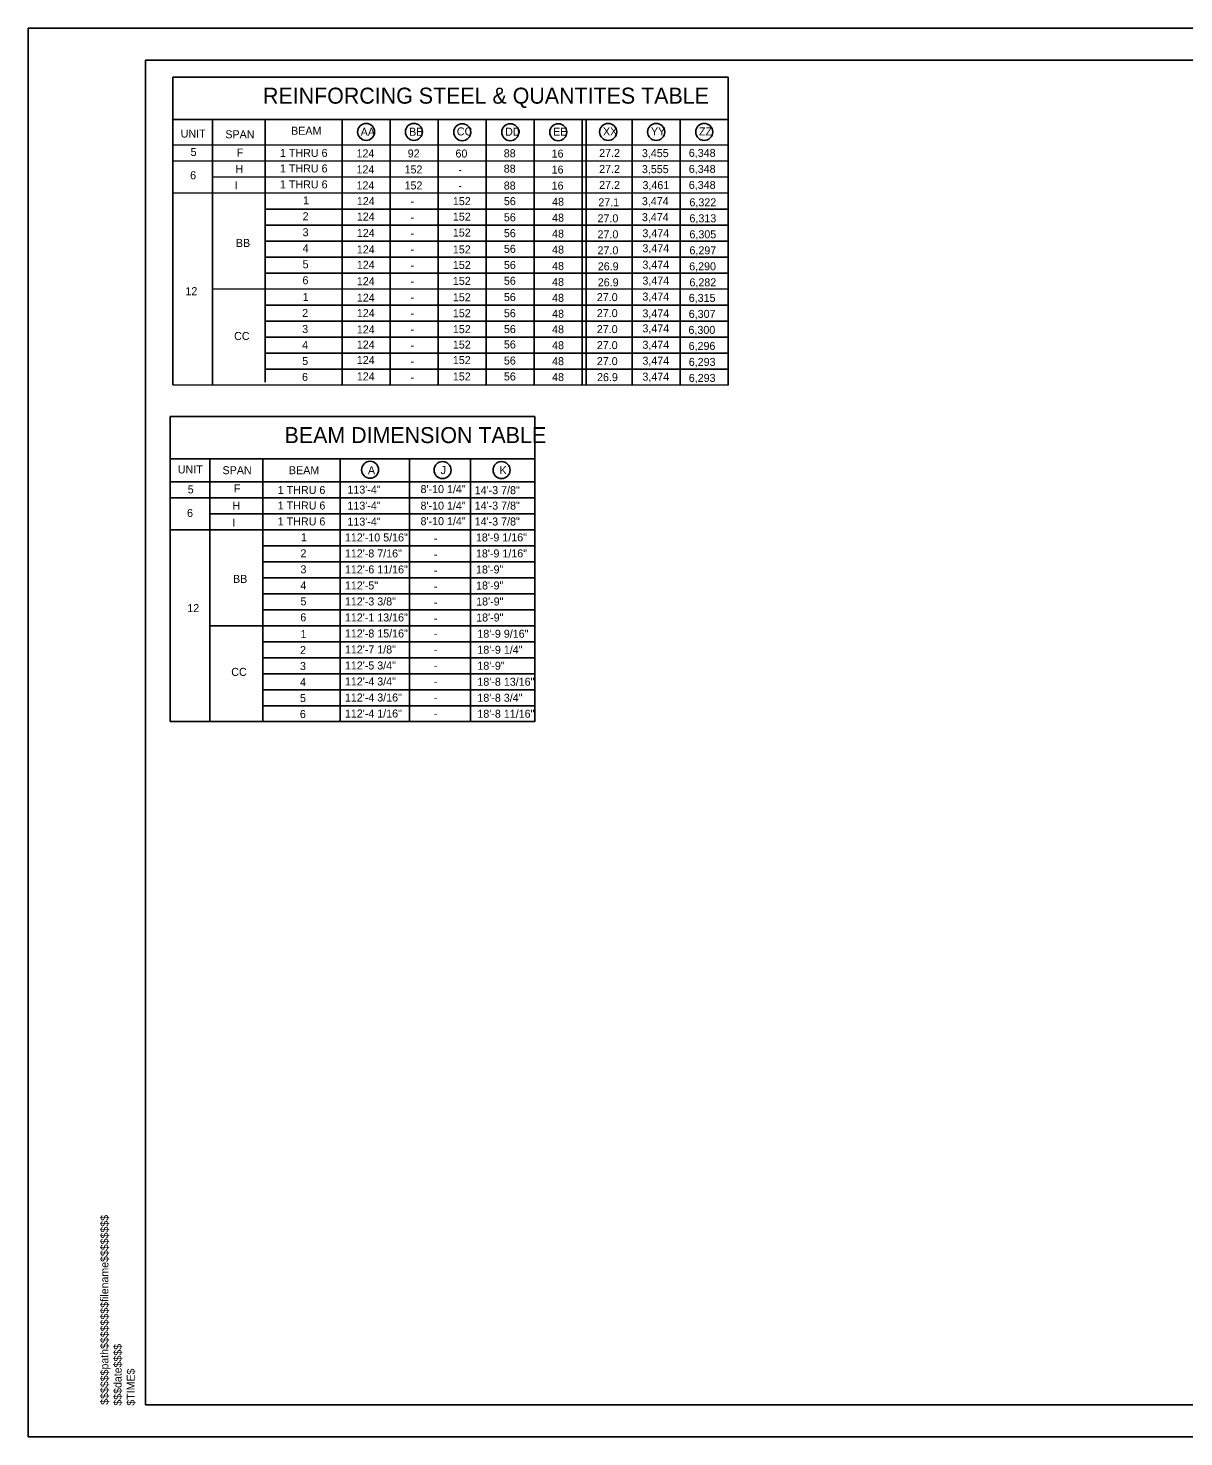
# Model space of a CAD drawing. Extents: x -55.6 to -19.5, y -100.1 to -78.1.
# Drawn here: x -55.58 to -37.53, y -100.12 to -78.12 of the extents above; entities that cross this region are included whole.
import ezdxf

# ---------------------------------------------------------------- set-up
doc = ezdxf.new("R2010")
doc.units = 0
for name, color, linetype in [('BR_AUTO DIMENSION', 7, 'Continuous'), ('BR_BORDER LINES', 7, 'Continuous'), ('BR_TABLE LINES', 7, 'Continuous'), ('BR_TEXT', 7, 'Continuous'), ('Level 31', 7, 'Continuous'), ('RD_SHT_ID', 7, 'Continuous')]:
    doc.layers.add(name, color=color, linetype=linetype)

msp = doc.modelspace()

# ---------------------------------------------------------------- linework, layer by layer
at = {"layer": 'BR_AUTO DIMENSION'}
for centre in [(-50.304, -79.741), (-49.557, -79.741), (-48.802, -79.746), (-48.052, -79.746), (-47.302, -79.746), (-46.523, -79.742), (-45.773, -79.742), (-45.023, -79.742), (-50.242, -85.018), (-49.11, -85.022), (-48.189, -85.022)]:
    msp.add_circle(centre, 0.133, dxfattribs=at)
at = {"layer": 'BR_BORDER LINES'}
for p, q in [((-20.084, -78.621), (-53.75, -78.621)), ((-53.75, -99.621), (-53.75, -78.621)), ((-53.322, -78.887), (-53.322, -83.693)), ((-53.322, -78.887), (-44.648, -78.887)), ((-44.648, -78.887), (-44.648, -83.696)), ((-53.322, -83.693), (-44.648, -83.696)), ((-53.367, -84.188), (-47.667, -84.186)), ((-53.367, -84.188), (-53.367, -88.951)), ((-47.667, -84.186), (-47.667, -88.954)), ((-53.367, -88.951), (-47.667, -88.949)), ((-53.75, -99.621), (-20.084, -99.621))]:
    msp.add_line(p, q, dxfattribs=at)
at = {"layer": 'BR_TABLE LINES'}
for p, q in [((-53.322, -79.546), (-44.648, -79.546)), ((-52.702, -79.546), (-52.702, -83.693)), ((-51.881, -79.548), (-51.881, -83.652)), ((-50.677, -79.549), (-50.677, -83.696)), ((-49.927, -79.552), (-49.927, -83.696)), ((-49.177, -79.553), (-49.177, -83.696)), ((-48.427, -79.553), (-48.427, -83.696)), ((-47.677, -79.554), (-47.677, -83.696)), ((-46.927, -79.555), (-46.927, -83.696)), ((-46.927, -79.555), (-46.927, -83.696)), ((-46.869, -79.555), (-46.869, -83.696)), ((-46.148, -79.553), (-46.148, -83.696)), ((-45.398, -79.554), (-45.398, -83.696)), ((-53.322, -79.943), (-44.648, -79.946)), ((-53.322, -80.193), (-44.648, -80.196)), ((-52.702, -80.443), (-44.648, -80.446)), ((-53.322, -80.693), (-44.648, -80.696)), ((-51.881, -80.946), (-44.648, -80.946)), ((-51.881, -80.946), (-44.648, -80.946)), ((-51.881, -81.196), (-44.648, -81.196)), ((-51.881, -81.446), (-44.648, -81.446)), ((-51.881, -81.696), (-44.648, -81.696)), ((-51.881, -81.946), (-44.648, -81.946)), ((-52.702, -82.193), (-44.648, -82.196)), ((-51.881, -82.446), (-44.648, -82.446)), ((-51.881, -82.696), (-44.648, -82.696)), ((-51.881, -82.946), (-44.648, -82.946)), ((-51.881, -83.196), (-44.648, -83.196)), ((-51.881, -83.446), (-44.648, -83.446)), ((-53.367, -84.847), (-47.667, -84.845)), ((-52.747, -84.848), (-52.747, -88.952)), ((-51.915, -84.848), (-51.915, -88.952)), ((-50.711, -84.849), (-50.711, -88.953)), ((-49.629, -84.85), (-49.629, -88.954)), ((-49.629, -84.85), (-49.629, -88.954)), ((-48.671, -84.85), (-48.671, -88.954)), ((-53.367, -85.206), (-47.667, -85.204)), ((-53.367, -85.456), (-47.667, -85.454)), ((-51.563, -85.456), (-48.876, -85.455)), ((-51.563, -85.456), (-48.876, -85.455)), ((-52.747, -85.706), (-47.667, -85.704)), ((-51.563, -85.706), (-48.876, -85.705)), ((-53.367, -85.956), (-47.667, -85.954)), ((-51.915, -86.206), (-47.667, -86.204)), ((-51.915, -86.456), (-47.667, -86.454)), ((-51.915, -86.706), (-47.667, -86.704)), ((-51.915, -86.956), (-47.667, -86.954)), ((-51.915, -87.206), (-47.667, -87.204)), ((-52.747, -87.456), (-47.667, -87.454)), ((-51.915, -87.706), (-47.667, -87.704)), ((-51.915, -87.956), (-47.667, -87.954)), ((-51.915, -88.206), (-47.667, -88.204)), ((-51.915, -88.456), (-47.667, -88.454)), ((-51.915, -88.706), (-47.667, -88.704))]:
    msp.add_line(p, q, dxfattribs=at)
at = {"layer": 'Level 31'}
msp.add_lwpolyline([(-55.583, -100.121), (-19.583, -100.121), (-19.583, -78.121), (-55.583, -78.121)], close=True, dxfattribs=at)

# ---------------------------------------------------------------- texts
at = {"layer": 'BR_TEXT'}
for s, height, p in [('REINFORCING STEEL & QUANTITES TABLE', 0.25, (-51.915, -79.3)), ('CC', 0.125, (-48.887, -79.796)), ('DD', 0.125, (-48.133, -79.8)), ('EE', 0.125, (-47.383, -79.8)), ('XX', 0.125, (-46.604, -79.796)), ('YY', 0.125, (-45.854, -79.796)), ('ZZ', 0.125, (-45.104, -79.796)), ('1 THRU 6', 0.125, (-51.65, -80.132)), ('124', 0.125, (-50.454, -80.139)), ('92', 0.125, (-49.654, -80.14)), ('60', 0.125, (-48.908, -80.141)), ('88', 0.125, (-48.154, -80.137)), ('16', 0.125, (-47.406, -80.142)), ('27.2', 0.125, (-46.664, -80.132)), ('3,455', 0.125, (-45.996, -80.135)), ('6,348', 0.125, (-45.263, -80.132)), ('1 THRU 6', 0.125, (-51.65, -80.374)), ('124', 0.125, (-50.454, -80.389)), ('152', 0.125, (-49.704, -80.39)), ('88', 0.125, (-48.154, -80.377)), ('16', 0.125, (-47.406, -80.392)), ('27.2', 0.125, (-46.664, -80.382)), ('3,555', 0.125, (-45.996, -80.385)), ('6,348', 0.125, (-45.263, -80.382)), ('1 THRU 6', 0.125, (-51.65, -80.623)), ('124', 0.125, (-50.454, -80.639)), ('152', 0.125, (-49.704, -80.64)), ('-', 0.125, (-48.863, -80.391)), ('88', 0.125, (-48.154, -80.641)), ('16', 0.125, (-47.406, -80.642)), ('27.2', 0.125, (-46.664, -80.632)), ('3,461', 0.125, (-45.987, -80.635)), ('6,348', 0.125, (-45.263, -80.632)), ('-', 0.125, (-48.863, -80.641)), ('1', 0.125, (-51.288, -80.871)), ('124', 0.125, (-50.449, -80.885)), ('-', 0.125, (-49.608, -80.887)), ('152', 0.125, (-48.949, -80.885)), ('56', 0.125, (-48.152, -80.885)), ('48', 0.125, (-47.399, -80.894)), ('27.1', 0.125, (-46.677, -80.903)), ('3,474', 0.125, (-45.996, -80.885)), ('6,322', 0.125, (-45.253, -80.903)), ('2', 0.125, (-51.296, -81.121)), ('124', 0.125, (-50.449, -81.126)), ('-', 0.125, (-49.608, -81.137)), ('152', 0.125, (-48.949, -81.127)), ('56', 0.125, (-48.152, -81.137)), ('48', 0.125, (-47.399, -81.143)), ('27.0', 0.125, (-46.689, -81.153)), ('3,474', 0.125, (-45.996, -81.135)), ('6,313', 0.125, (-45.253, -81.153)), ('3', 0.125, (-51.296, -81.371)), ('124', 0.125, (-50.449, -81.382)), ('-', 0.125, (-49.608, -81.387)), ('152', 0.125, (-48.949, -81.376)), ('56', 0.125, (-48.152, -81.385)), ('48', 0.125, (-47.399, -81.392)), ('27.0', 0.125, (-46.689, -81.403)), ('3,474', 0.125, (-45.988, -81.386)), ('6,305', 0.125, (-45.253, -81.403)), ('4', 0.125, (-51.296, -81.621)), ('124', 0.125, (-50.449, -81.639)), ('-', 0.125, (-49.608, -81.637)), ('152', 0.125, (-48.949, -81.639)), ('56', 0.125, (-48.152, -81.63)), ('48', 0.125, (-47.399, -81.641)), ('27.0', 0.125, (-46.689, -81.653)), ('3,474', 0.125, (-45.988, -81.621)), ('6,297', 0.125, (-45.253, -81.653)), ('5', 0.125, (-51.296, -81.871)), ('124', 0.125, (-50.449, -81.879)), ('-', 0.125, (-49.608, -81.887)), ('152', 0.125, (-48.949, -81.881)), ('56', 0.125, (-48.152, -81.882)), ('48', 0.125, (-47.399, -81.897)), ('26.9', 0.125, (-46.685, -81.903)), ('3,474', 0.125, (-45.988, -81.877)), ('6,290', 0.125, (-45.257, -81.903)), ('6', 0.125, (-51.298, -82.121)), ('124', 0.125, (-50.449, -82.135)), ('152', 0.125, (-48.949, -82.13)), ('56', 0.125, (-48.152, -82.129)), ('48', 0.125, (-47.399, -82.146)), ('26.9', 0.125, (-46.685, -82.153)), ('3,474', 0.125, (-45.988, -82.126)), ('6,282', 0.125, (-45.253, -82.153)), ('1', 0.125, (-51.295, -82.382)), ('124', 0.125, (-50.449, -82.393)), ('-', 0.125, (-49.608, -82.137)), ('152', 0.125, (-48.949, -82.386)), ('56', 0.125, (-48.152, -82.383)), ('48', 0.125, (-47.399, -82.395)), ('27.0', 0.125, (-46.7, -82.384)), ('3,474', 0.125, (-45.988, -82.375)), ('6,315', 0.125, (-45.264, -82.396)), ('-', 0.125, (-49.608, -82.387)), ('2', 0.125, (-51.303, -82.632)), ('124', 0.125, (-50.449, -82.633)), ('-', 0.125, (-49.608, -82.637)), ('152', 0.125, (-48.949, -82.635)), ('56', 0.125, (-48.152, -82.635)), ('48', 0.125, (-47.399, -82.644)), ('27.0', 0.125, (-46.7, -82.634)), ('3,474', 0.125, (-45.988, -82.638)), ('6,307', 0.125, (-45.264, -82.646)), ('3', 0.125, (-51.303, -82.882)), ('124', 0.125, (-50.449, -82.889)), ('-', 0.125, (-49.608, -82.887)), ('152', 0.125, (-48.949, -82.884)), ('56', 0.125, (-48.152, -82.883)), ('48', 0.125, (-47.399, -82.886)), ('27.0', 0.125, (-46.7, -82.884)), ('3,474', 0.125, (-45.988, -82.872)), ('6,300', 0.125, (-45.268, -82.896)), ('4', 0.125, (-51.303, -83.132)), ('124', 0.125, (-50.449, -83.125)), ('-', 0.125, (-49.608, -83.137)), ('152', 0.125, (-48.949, -83.125)), ('56', 0.125, (-48.152, -83.123)), ('48', 0.125, (-47.399, -83.135)), ('27.0', 0.125, (-46.7, -83.134)), ('3,474', 0.125, (-45.988, -83.128)), ('6,296', 0.125, (-45.266, -83.146)), ('5', 0.125, (-51.303, -83.382)), ('124', 0.125, (-50.449, -83.366)), ('-', 0.125, (-49.608, -83.387)), ('152', 0.125, (-48.949, -83.367)), ('56', 0.125, (-48.152, -83.375)), ('48', 0.125, (-47.399, -83.384)), ('27.0', 0.125, (-46.7, -83.384)), ('3,474', 0.125, (-45.988, -83.377)), ('6,293', 0.125, (-45.264, -83.396)), ('6', 0.125, (-51.305, -83.632)), ('124', 0.125, (-50.449, -83.622)), ('-', 0.125, (-49.608, -83.637)), ('152', 0.125, (-48.949, -83.623)), ('56', 0.125, (-48.152, -83.623)), ('48', 0.125, (-47.399, -83.633)), ('26.9', 0.125, (-46.697, -83.634)), ('3,474', 0.125, (-45.988, -83.626)), ('6,293', 0.125, (-45.264, -83.646)), ('BEAM DIMENSION TABLE', 0.25, (-51.578, -84.601)), ('J', 0.125, (-49.14, -85.086)), ('K', 0.125, (-48.219, -85.086)), ('1 THRU 6', 0.125, (-51.684, -85.396)), ('113\'-4"', 0.125, (-50.596, -85.39)), ('8\'-10 1/4"', 0.125, (-49.454, -85.382)), ('14\'-3 7/8"', 0.125, (-48.608, -85.399)), ('1 THRU 6', 0.125, (-51.684, -85.638)), ('113\'-4"', 0.125, (-50.596, -85.64)), ('8\'-10 1/4"', 0.125, (-49.454, -85.641)), ('14\'-3 7/8"', 0.125, (-48.608, -85.64)), ('1 THRU 6', 0.125, (-51.684, -85.887)), ('113\'-4"', 0.125, (-50.596, -85.89)), ('8\'-10 1/4"', 0.125, (-49.454, -85.883)), ('14\'-3 7/8"', 0.125, (-48.608, -85.888)), ('1', 0.125, (-51.322, -86.135)), ('112\'-10 5/16"', 0.125, (-50.636, -86.137)), ('-', 0.125, (-49.245, -86.15)), ('2', 0.125, (-51.33, -86.385)), ('112\'-8 7/16"', 0.125, (-50.636, -86.387)), ('-', 0.125, (-49.245, -86.4)), ('3', 0.125, (-51.33, -86.635)), ('112\'-6 11/16"', 0.125, (-50.636, -86.637)), ('-', 0.125, (-49.245, -86.65)), ('4', 0.125, (-51.33, -86.885)), ('112\'-5"', 0.125, (-50.636, -86.887)), ('-', 0.125, (-49.245, -86.9)), ('5', 0.125, (-51.33, -87.135)), ('112\'-3 3/8"', 0.125, (-50.636, -87.137)), ('-', 0.125, (-49.245, -87.15)), ('6', 0.125, (-51.332, -87.385)), ('112\'-1 13/16"', 0.125, (-50.636, -87.387)), ('1', 0.125, (-51.329, -87.646)), ('112\'-8 15/16"', 0.125, (-50.636, -87.637)), ('-', 0.125, (-49.245, -87.4)), ('2', 0.125, (-51.337, -87.896)), ('112\'-7 1/8"', 0.125, (-50.636, -87.887)), ('-', 0.125, (-49.245, -87.636)), ('-', 0.125, (-49.245, -87.886)), ('3', 0.125, (-51.337, -88.146)), ('112\'-5 3/4"', 0.125, (-50.636, -88.137)), ('-', 0.125, (-49.245, -88.136)), ('4', 0.125, (-51.337, -88.396)), ('112\'-4 3/4"', 0.125, (-50.636, -88.387)), ('-', 0.125, (-49.245, -88.386)), ('5', 0.125, (-51.337, -88.646)), ('112\'-4 3/16"', 0.125, (-50.636, -88.637)), ('-', 0.125, (-49.245, -88.636)), ('6', 0.125, (-51.339, -88.896)), ('112\'-4 1/16"', 0.125, (-50.636, -88.887)), ('-', 0.125, (-49.245, -88.886))]:
    msp.add_text(s, height=height, dxfattribs=at).set_placement(p)
for s, rotation, p in [('UNIT', 360, (-53.201, -79.83)), ('SPAN', 360, (-52.503, -79.841)), ('BEAM', 360, (-51.476, -79.786)), ('AA', 360, (-50.389, -79.801)), ('BB', 360, (-49.633, -79.801)), ('5', 360, (-53.046, -80.117)), ('F', 360, (-52.325, -80.126)), ('H', 360, (-52.346, -80.383)), ('6', 360, (-53.053, -80.481)), ('I', 360, (-52.358, -80.638)), ('BB', 360, (-52.338, -81.538)), ('12', 360, (-53.127, -82.291)), ('CC', 360, (-52.366, -82.991)), ('UNIT', 360, (-53.246, -85.075)), ('SPAN', 360, (-52.547, -85.087)), ('BEAM', 360, (-51.51, -85.087)), ('A', 360, (-50.276, -85.088)), ('5', 360, (-53.091, -85.387)), ('F', 360, (-52.369, -85.372)), ('H', 360, (-52.39, -85.639)), ('6', 360, (-53.101, -85.755)), ('I', 360, (-52.396, -85.908)), ('18\'-9 1/16"', 0.1943, (-48.589, -86.138)), ('18\'-9 1/16"', 0.1943, (-48.588, -86.388)), ('BB', 360, (-52.383, -86.784)), ('18\'-9"', 0.1943, (-48.587, -86.638)), ('18\'-9"', 0.1943, (-48.586, -86.888)), ('12', 360, (-53.097, -87.241)), ('18\'-9"', 0.1943, (-48.585, -87.138)), ('18\'-9"', 0.1943, (-48.585, -87.388)), ('18\'-9 9/16"', 360, (-48.566, -87.641)), ('18\'-9 1/4"', 360, (-48.566, -87.891)), ('CC', 360, (-52.411, -88.237)), ('18\'-9"', 360, (-48.566, -88.141)), ('18\'-8 13/16"', 360, (-48.566, -88.391)), ('18\'-8 3/4"', 360, (-48.566, -88.641)), ('18\'-8 11/16"', 360, (-48.566, -88.891))]:
    msp.add_text(s, height=0.125, rotation=rotation, dxfattribs=at).set_placement(p)
at = {"layer": 'RD_SHT_ID'}
for s, height, p in [('$$$$$$path$$$$$$$$filename$$$$$$$$', 0.12347, (-54.33, -99.621)), ('$$$date$$$$', 0.12347, (-54.124, -99.634)), ('$TIME$', 0.1235, (-53.919, -99.634))]:
    msp.add_text(s, height=height, rotation=90, dxfattribs=at).set_placement(p)

doc.saveas('drawing.dxf')
